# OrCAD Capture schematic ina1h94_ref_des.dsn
size A
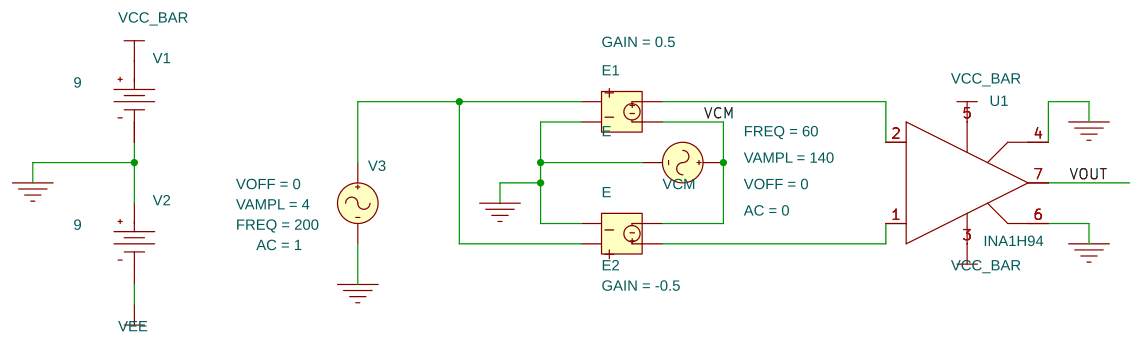
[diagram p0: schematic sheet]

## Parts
E1  E
E2  E
U1  INA1H94
V1  VDC
V2  VDC
V3  VSIN
VCM  VSIN

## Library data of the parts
E1 = E: GAIN: 0.5
E2 = E: GAIN: -0.5
U1 = INA1H94_3: PSpiceTemplate: X^@REFDES  %+ %- %REFA %REFB %V+ %V- %Vout @MODEL
V1 V2 = VDC: DC: 9
V3 = VSIN: AC: 1; FREQ: 200; VAMPL: 4; VOFF: 0
VCM = VSIN: AC: 0; FREQ: 60; VAMPL: 140; VOFF: 0

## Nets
Vcc: U1.5(V+) V1.0(+)
Vee: U1.3(V-) V2.1(-)
0: E1.2 E2.2 U1.4(REFA) U1.6(REFB) V1.1(-) V2.0(+) V3.2(-) VCM.2(-)
VCM: E1.4 E2.4 VCM.1(+)
VOUT: U1.7(Vout)
N00971: E2.3 U1.1(+)
N00988: E1.3 U1.2(-)
N01752: E1.1 E2.1 V3.1(+)
